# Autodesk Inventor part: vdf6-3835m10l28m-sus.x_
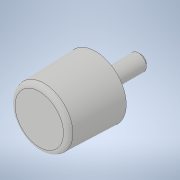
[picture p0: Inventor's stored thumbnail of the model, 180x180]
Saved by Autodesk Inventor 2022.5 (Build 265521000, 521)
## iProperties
Created: 2021-08
Part Number: vdf6-3835m10l28m-sus.x_
Material: 一般
Document SubType Name: Modeling
Designer: ImaoCorp
Density: 1 g/cm^3
Appearance: 既定
Sending System: SOLIDWORKS 2019-2019304
MC: AMD64
MC_MODEL: Intel64 Family 6 Model 60 Stepping 3, GenuineIntel
OS: Windows_NT
FRU: Parasolid Version 31.0, build 290,  9- 1-2019
FORMAT: text
GUISE: transmit
KEY: vdf6-3835m10l28m-sus
FILE: vdf6-3835m10l28m-sus.x_t
DATE: Wed Aug 11 14:58:52 2021
Author: ImaoCorp
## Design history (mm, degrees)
feature "Base1"
node "ソリッド1"
